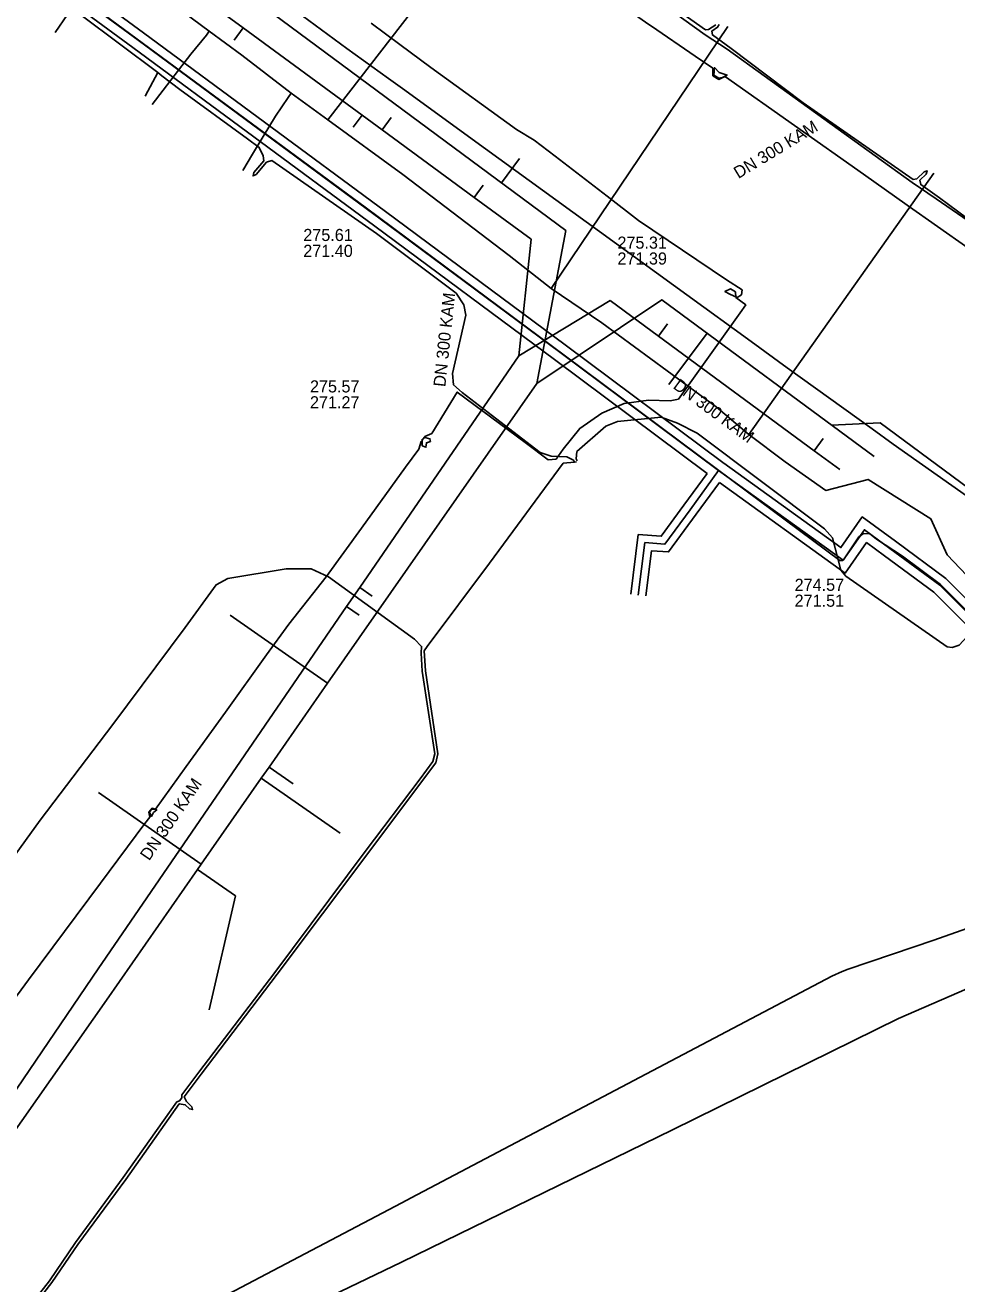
# Model space of a CAD drawing. Extents: x -598233 to -596890, y -1157848 to -1156431.
# Drawn here: x -597538.8 to -597477.2, y -1156886.7 to -1156803.5 of the extents above; entities that cross this region are included whole.
import ezdxf

# ---------------------------------------------------------------- set-up
doc = ezdxf.new("R2010")
doc.units = 0
for name, color, linetype in [('Vrstva 1', 7, 'Continuous'), ('Vrstva 13', 7, 'Continuous'), ('Vrstva 19', 7, 'Continuous'), ('Vrstva 25', 7, 'Continuous'), ('Vrstva 26', 7, 'Continuous'), ('Vrstva 42', 7, 'Continuous'), ('Vrstva 44', 7, 'Continuous'), ('Vrstva 5', 7, 'Continuous'), ('Vrstva 55', 7, 'Continuous'), ('Vrstva 8', 7, 'Continuous')]:
    doc.layers.add(name, color=color, linetype=linetype)

msp = doc.modelspace()

# ---------------------------------------------------------------- linework, layer by layer
at = {"layer": 'Vrstva 1'}
for points in [[(-597537.15, -1156791.82), (-597503.03, -1156817.1), (-597504.95, -1156827.2)], [(-597507.293, -1156813.941), (-597506.087, -1156812.34)], [(-597504.95, -1156827.2), (-597496.69, -1156821.67), (-597482.66, -1156832.04)], [(-597493.69, -1156823.887), (-597496.217, -1156827.272)], [(-597546.37, -1156886.45), (-597533.4, -1156867.979), (-597527.374, -1156859.341), (-597527.128, -1156858.989), (-597523.162, -1156853.304), (-597522.645, -1156852.564), (-597518.783, -1156847.028), (-597504.95, -1156827.2)], [(-597485.463, -1156829.968), (-597482.266, -1156829.809), (-597472.701, -1156836.881)], [(-597525.23, -1156842.53), (-597518.783, -1156847.028)], [(-597521.06, -1156853.67), (-597522.645, -1156852.564)], [(-597517.95, -1156856.94), (-597523.162, -1156853.304)], [(-597533.92, -1156854.25), (-597527.128, -1156858.989)], [(-597527.374, -1156859.341), (-597524.864, -1156861.092), (-597526.61, -1156868.63)]]:
    msp.add_lwpolyline(points, dxfattribs=at)
at = {"layer": 'Vrstva 13'}
for points in [[(-597521.27, -1156802.291), (-597517.51, -1156805.05), (-597514.751, -1156807.047), (-597513.831, -1156807.694), (-597508.339, -1156811.688), (-597495.04, -1156821.341), (-597490.791, -1156824.428), (-597488.41, -1156826.18), (-597482.79, -1156830.208), (-597481.39, -1156831.21), (-597476.54, -1156834.64), (-597471.76, -1156838.15), (-597467.02, -1156841.68), (-597456.73, -1156849.38), (-597454.49, -1156851.03), (-597453.804, -1156854.64), (-597453.718, -1156854.985)], [(-597542.831, -1156896.557), (-597538.61, -1156894.41), (-597538.4, -1156894.3), (-597538.21, -1156894.19), (-597527.5, -1156888.55), (-597513.869, -1156881.371), (-597513.256, -1156881.049), (-597485.46, -1156866.4), (-597484.76, -1156866.08), (-597484.59, -1156866.01), (-597484.44, -1156865.95), (-597481.432, -1156864.929), (-597478.72, -1156864.01), (-597468.8, -1156860.52), (-597453.62, -1156855.38)]]:
    msp.add_lwpolyline(points, dxfattribs=at)
at = {"layer": 'Vrstva 19'}
for points in [[(-597518.77, -1156809.78), (-597506.32, -1156793.68)], [(-597533.26, -1156798.96), (-597533.48, -1156799.21), (-597534.25, -1156800.32), (-597535.212, -1156801.712), (-597535.97, -1156802.81), (-597536.8, -1156803.99)], [(-597532.47, -1156799.55), (-597526.61, -1156803.91), (-597524.443, -1156805.509), (-597521.19, -1156808.01), (-597518.77, -1156809.78), (-597513.813, -1156813.398), (-597506.785, -1156818.742), (-597504.01, -1156820.92), (-597500.646, -1156823.192), (-597493.102, -1156828.761), (-597490.93, -1156830.57), (-597488.546, -1156832.385), (-597485.845, -1156834.278), (-597483.06, -1156833.544), (-597478.901, -1156836.151), (-597477.839, -1156838.542), (-597475.67, -1156840.81)], [(-597504.01, -1156820.92), (-597492.33, -1156803.6)], [(-597526.61, -1156803.91), (-597526.78, -1156804.18), (-597527.82, -1156805.44), (-597528.627, -1156806.485), (-597529.65, -1156807.81), (-597530.37, -1156808.76)], [(-597521.19, -1156808.01), (-597521.39, -1156808.3), (-597522.22, -1156809.53), (-597523.03, -1156810.867), (-597523.74, -1156812.04), (-597524.39, -1156813.13)], [(-597490.93, -1156830.57), (-597478.71, -1156813.31)], [(-597604.52, -1156929.9), (-597589.51, -1156924.13), (-597583.87, -1156921.72), (-597583.52, -1156921.52), (-597578.38, -1156918.96), (-597567.93, -1156912.7), (-597557.6, -1156906.71), (-597549.49, -1156903.16), (-597531.57, -1156893.81), (-597531.39, -1156893.72), (-597530.7, -1156893.37), (-597525.62, -1156890.94), (-597525.12, -1156890.69), (-597524.81, -1156890.54), (-597513.9, -1156885.31), (-597495.98, -1156876.55), (-597481.04, -1156869.19), (-597476.52, -1156867.24), (-597471.95, -1156865.46), (-597449.72, -1156857.53), (-597426.05, -1156849.47), (-597422.869, -1156848.293), (-597402.78, -1156841.65)]]:
    msp.add_lwpolyline(points, dxfattribs=at)
at = {"layer": 'Vrstva 25'}
msp.add_line((-597492.937, -1156832.966), (-597494.824, -1156835.55), dxfattribs=at)
for points in [[(-597492.937, -1156832.966), (-597503.426, -1156825.135), (-597515.308, -1156816.317), (-597531.297, -1156804.513), (-597548.577, -1156791.841), (-597578.918, -1156769.561), (-597598.068, -1156755.348), (-597616.395, -1156741.766), (-597633.981, -1156728.852)], [(-597481.608, -1156838.12), (-597483.297, -1156836.873), (-597484.71, -1156838.898), (-597492.937, -1156832.966)], [(-597494.824, -1156835.55), (-597496.487, -1156837.821), (-597497.807, -1156837.731), (-597498.242, -1156841.194)], [(-597402.772, -1156837.165), (-597425.102, -1156844.405), (-597448.213, -1156851.888), (-597466.757, -1156857.728), (-597467.583, -1156855.384), (-597468.2, -1156853.876), (-597469.666, -1156850.953), (-597471.213, -1156848.467), (-597473.531, -1156845.345), (-597478.312, -1156840.551), (-597481.608, -1156838.12)]]:
    msp.add_lwpolyline(points, dxfattribs=at)
at = {"layer": 'Vrstva 26'}
for p, q in [((-597495.228, -1156835.255), (-597493.692, -1156833.152)), ((-597492.886, -1156833.743), (-597494.42, -1156835.845))]:
    msp.add_line(p, q, dxfattribs=at)
for points in [[(-597633.226, -1156728.662), (-597616.039, -1156741.283), (-597597.711, -1156754.866), (-597578.562, -1156769.078), (-597548.222, -1156791.357), (-597530.941, -1156804.03), (-597514.951, -1156815.835), (-597503.068, -1156824.654), (-597492.578, -1156832.486)], [(-597493.692, -1156833.152), (-597503.784, -1156825.616), (-597515.665, -1156816.8), (-597531.652, -1156804.997), (-597548.932, -1156792.325), (-597579.275, -1156770.044), (-597598.426, -1156755.83), (-597616.752, -1156742.249), (-597634.336, -1156729.336)], [(-597492.586, -1156832.48), (-597484.853, -1156838.055), (-597483.437, -1156836.025), (-597481.252, -1156837.637)], [(-597481.964, -1156838.603), (-597483.158, -1156837.722), (-597484.566, -1156839.742), (-597492.886, -1156833.743)], [(-597498.738, -1156841.132), (-597498.245, -1156837.2), (-597496.727, -1156837.303), (-597495.227, -1156835.255)], [(-597494.42, -1156835.846), (-597496.246, -1156838.338), (-597497.37, -1156838.262), (-597497.746, -1156841.256)], [(-597481.252, -1156837.637), (-597477.919, -1156840.095), (-597473.075, -1156844.953), (-597470.716, -1156848.129), (-597469.142, -1156850.659), (-597467.654, -1156853.627), (-597467.022, -1156855.17), (-597466.384, -1156856.981), (-597448.395, -1156851.316), (-597425.287, -1156843.834), (-597402.971, -1156836.599)], [(-597402.573, -1156837.732), (-597424.917, -1156844.976), (-597448.03, -1156852.459), (-597467.13, -1156858.474), (-597468.144, -1156855.597), (-597468.747, -1156854.125), (-597470.19, -1156851.246), (-597471.709, -1156848.804), (-597473.986, -1156845.738), (-597478.705, -1156841.007), (-597481.964, -1156838.603)]]:
    msp.add_lwpolyline(points, dxfattribs=at)
at = {"layer": 'Vrstva 42'}
for points in [[(-597466.71, -1156857.63), (-597467.51, -1156855.36), (-597468.13, -1156853.85), (-597469.6, -1156850.91), (-597471.15, -1156848.42), (-597473.47, -1156845.3), (-597478.26, -1156840.49), (-597480.79, -1156838.62), (-597482.51, -1156837.5), (-597482.94, -1156837.15), (-597483.35, -1156837.12), (-597483.66, -1156837.34), (-597484.68, -1156838.86), (-597484.75, -1156838.91), (-597484.92, -1156838.91), (-597493.01, -1156832.89), (-597503.05, -1156825.39), (-597516.22, -1156815.61), (-597540.24, -1156797.88), (-597551.7, -1156789.52), (-597576.08, -1156771.63), (-597580.61, -1156768.3), (-597603.52, -1156751.29)], [(-597501.02, -1156798.71), (-597493.81, -1156803.83), (-597493.602, -1156803.81), (-597493.112, -1156803.487)], [(-597502.441, -1156832.427), (-597502.455, -1156832.402), (-597502.531, -1156832.272), (-597502.97, -1156832.06), (-597504, -1156832.02), (-597504.73, -1156831.77), (-597509.88, -1156827.81), (-597510.45, -1156827.3), (-597510.52, -1156826.55), (-597509.64, -1156822.7), (-597509.78, -1156822.01), (-597510.29, -1156821.24), (-597515.55, -1156817.3), (-597522.46, -1156812.47), (-597522.819, -1156812.572), (-597523.505, -1156813.391), (-597523.71, -1156813.48), (-597523.658, -1156813.262), (-597523.005, -1156812.482), (-597523.04, -1156812.16), (-597523.3, -1156811.6), (-597524.07, -1156811.04), (-597528.54, -1156807.76), (-597529.74, -1156806.86), (-597530.01, -1156806.65), (-597535.07, -1156802.85)], [(-597492.89, -1156803.46), (-597493.002, -1156803.654), (-597493.378, -1156803.902), (-597493.35, -1156804.16), (-597492.1, -1156805.05), (-597487.35, -1156808.64), (-597480.08, -1156813.71), (-597479.829, -1156813.674), (-597479.353, -1156813.217), (-597479.14, -1156813.15), (-597479.215, -1156813.361), (-597479.634, -1156813.764), (-597479.57, -1156814.05), (-597478.34, -1156814.94), (-597472.97, -1156818.89)], [(-597530.01, -1156806.65), (-597530.83, -1156808.2)], [(-597467.44, -1156830.93), (-597469.02, -1156833.73), (-597470.95, -1156836.8), (-597471.34, -1156837.61), (-597474.22, -1156841.51), (-597475.07, -1156842.57), (-597475.68, -1156843.06), (-597477.03, -1156844.51), (-597477.49, -1156844.67), (-597477.83, -1156844.62), (-597484.52, -1156839.95), (-597484.85, -1156839.54), (-597485.41, -1156837.41), (-597485.94, -1156836.82), (-597494.36, -1156830.49), (-597495.66, -1156829.82), (-597496.74, -1156829.43), (-597499.63, -1156829.71), (-597500.4, -1156830.02), (-597502.31, -1156831.71), (-597502.354, -1156832.179), (-597502.275, -1156832.312)], [(-597538.761, -1156888.901), (-597537.009, -1156886.659), (-597535.288, -1156884.128), (-597532.129, -1156879.829), (-597528.591, -1156874.829), (-597528.19, -1156874.899), (-597527.909, -1156875.161), (-597527.71, -1156875.21), (-597527.76, -1156875.026), (-597528.116, -1156874.688), (-597528.254, -1156874.374), (-597527.13, -1156872.87), (-597522.11, -1156866.27), (-597516.13, -1156858.28), (-597512.5, -1156853.46), (-597511.637, -1156852.293), (-597511.498, -1156851.694), (-597512.32, -1156846.21), (-597512.398, -1156844.889), (-597512.21, -1156844.6), (-597508.07, -1156839.08), (-597503.21, -1156832.48), (-597502.455, -1156832.402), (-597502.34, -1156832.39)], [(-597543.04, -1156863.36), (-597537.77, -1156856.09), (-597532.98, -1156849.76), (-597528.19, -1156843.33), (-597526.15, -1156840.51), (-597525.37, -1156840.11), (-597521.52, -1156839.46), (-597519.86, -1156839.47), (-597518.72, -1156839.99), (-597513.03, -1156844.11), (-597512.57, -1156844.59), (-597512.59, -1156845.036), (-597512.52, -1156846.23), (-597511.702, -1156851.686), (-597511.823, -1156852.207), (-597512.66, -1156853.34), (-597516.29, -1156858.16), (-597522.27, -1156866.15), (-597527.29, -1156872.75), (-597528.407, -1156874.246), (-597528.422, -1156874.435), (-597528.567, -1156874.63), (-597528.745, -1156874.7), (-597532.291, -1156879.712), (-597535.452, -1156884.012), (-597537.171, -1156886.541), (-597538.919, -1156888.779)]]:
    msp.add_lwpolyline(points, dxfattribs=at)
at = {"layer": 'Vrstva 44'}
msp.add_lwpolyline([(-597465.79, -1156829.26), (-597464.78, -1156827.99), (-597464.704, -1156827.467), (-597464.374, -1156826.961), (-597464.181, -1156825.995), (-597464.238, -1156825.407), (-597464.434, -1156824.987), (-597464.7, -1156824.63), (-597466.19, -1156823.67), (-597472.2, -1156819.36), (-597478.55, -1156814.99), (-597480.14, -1156813.91), (-597492.36, -1156805.1), (-597493.83, -1156804.15), (-597499.87, -1156799.78)], dxfattribs=at)
at = {"layer": 'Vrstva 5'}
for p, q in [((-597524.955, -1156804.503), (-597524.364, -1156803.697)), ((-597517.097, -1156810.267), (-597516.506, -1156809.461)), ((-597514.589, -1156809.627), (-597515.18, -1156810.434)), ((-597508.499, -1156814.095), (-597509.09, -1156814.901)), ((-597505.33, -1156817.66), (-597506.15, -1156825.38)), ((-597500.11, -1156821.71), (-597506.15, -1156825.38)), ((-597496.313, -1156823.265), (-597496.906, -1156824.071)), ((-597486.023, -1156830.845), (-597486.616, -1156831.651)), ((-597515.833, -1156841.265), (-597516.658, -1156840.699)), ((-597516.697, -1156842.525), (-597517.522, -1156841.959))]:
    msp.add_line(p, q, dxfattribs=at)
for points in [[(-597540.28, -1156792.02), (-597537.347, -1156794.171), (-597530.888, -1156798.91), (-597528.895, -1156800.372), (-597524.364, -1156803.697), (-597516.506, -1156809.461), (-597515.18, -1156810.434), (-597509.09, -1156814.901), (-597505.33, -1156817.66)], [(-597484.92, -1156832.9), (-597486.616, -1156831.651), (-597496.906, -1156824.071), (-597500.11, -1156821.71)], [(-597506.15, -1156825.38), (-597516.658, -1156840.699), (-597517.522, -1156841.959), (-597533.95, -1156865.91)], [(-597533.95, -1156865.91), (-597539.73, -1156874.417), (-597546.06, -1156883.735), (-597546.75, -1156884.75)]]:
    msp.add_lwpolyline(points, dxfattribs=at)
at = {"layer": 'Vrstva 55'}
for points in [[(-597514.86, -1156791.16), (-597515.17, -1156790.78), (-597515.24, -1156791.26), (-597514.89, -1156791.49), (-597514.458, -1156791.458), (-597511.27, -1156793.82), (-597511.197, -1156793.871), (-597508.319, -1156795.9), (-597507.95, -1156796.16), (-597497.54, -1156803.47), (-597497.371, -1156803.586), (-597494.488, -1156805.562), (-597493.312, -1156806.367), (-597493.312, -1156806.86), (-597492.91, -1156807.1), (-597492.38, -1156806.82), (-597492.9, -1156806.65)], [(-597515.9, -1156803.38), (-597514, -1156804.79), (-597511.96, -1156806.31), (-597506.29, -1156810.42), (-597505.12, -1156811.11), (-597503.74, -1156812.17), (-597500.31, -1156814.82)], [(-597492.9, -1156806.65), (-597493.21, -1156806.32), (-597493.25, -1156806.82), (-597492.92, -1156807.02), (-597492.491, -1156806.938), (-597483.359, -1156813.377), (-597480.478, -1156815.408), (-597472.459, -1156821.062), (-597472.41, -1156821.46), (-597472.11, -1156821.68), (-597471.46, -1156821.55), (-597472.05, -1156821.35)], [(-597500.31, -1156814.82), (-597498.24, -1156816.42), (-597492.41, -1156820.36), (-597491.38, -1156821.02), (-597491.43, -1156821.34), (-597491.7, -1156821.53), (-597492.19, -1156821.29)], [(-597540.885, -1156869.787), (-597538.542, -1156866.637), (-597533.788, -1156860.247), (-597530.86, -1156856.31), (-597530.54, -1156855.88), (-597530.602, -1156855.55), (-597530.388, -1156855.291), (-597530.071, -1156855.401), (-597530.29, -1156855.58), (-597530.412, -1156855.835), (-597530.549, -1156855.561), (-597530.38, -1156855.355), (-597530.16, -1156855.35), (-597528.124, -1156852.526), (-597525.532, -1156848.931), (-597522.811, -1156845.157), (-597521.35, -1156843.13), (-597518.88, -1156840), (-597516.547, -1156836.779), (-597513.624, -1156832.743), (-597512.76, -1156831.55), (-597512.6, -1156831.048), (-597512.361, -1156830.786), (-597512.016, -1156830.865), (-597511.985, -1156831.037), (-597512.25, -1156831.12), (-597512.283, -1156831.427), (-597512.52, -1156831.325), (-597512.54, -1156830.9), (-597512.358, -1156830.714), (-597511.9, -1156830.51), (-597510.21, -1156827.77), (-597505.721, -1156831.116), (-597504.2, -1156832.25), (-597503.68, -1156832.2), (-597503.21, -1156831.54), (-597502.11, -1156830.18), (-597500.65, -1156829.17), (-597499.17, -1156828.54), (-597497.56, -1156828.31), (-597496.14, -1156828.36), (-597495.59, -1156828.24), (-597491.515, -1156822.535), (-597491.14, -1156822.01), (-597491.797, -1156821.51), (-597491.826, -1156821.157), (-597492.139, -1156820.943), (-597492.514, -1156821.121), (-597492.19, -1156821.29)]]:
    msp.add_lwpolyline(points, dxfattribs=at)

# ---------------------------------------------------------------- texts
at = {"layer": 'Vrstva 8'}
for rotation, p in [(31.28353, (-597491.628, -1156813.69)), (83.93691, (-597511.001, -1156827.458)), (323.62208, (-597495.999, -1156827.485)), (55.55332, (-597530.58, -1156858.806))]:
    msp.add_text('DN 300 KAM', height=0.8, rotation=rotation, dxfattribs=at).set_placement(p)
for s, p in [('275.61', (-597520.389, -1156817.786)), ('275.31', (-597499.623, -1156818.293)), ('271.40', (-597520.389, -1156818.836)), ('271.39', (-597499.623, -1156819.343)), ('275.57', (-597519.946, -1156827.798)), ('271.27', (-597519.946, -1156828.848)), ('274.57', (-597487.911, -1156840.916)), ('271.51', (-597487.911, -1156841.966))]:
    msp.add_text(s, height=0.8, dxfattribs=at).set_placement(p)

doc.saveas('drawing.dxf')
